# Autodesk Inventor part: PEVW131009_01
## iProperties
Created: 2009-10
Part Number: PEVW131009_01
Cost Center: 0 kg
Material: 1.0037 St 37-2
Document SubType Name: Blech
Designer: Student_TAB
Authority: 0 mm^3
Density: 7.85 g/cm^3
Description: Test Abgeleitete Komponente iPart
Mass: 200.159 g
Surface Area: 687.763 cm^2
Volume: 25.498 cm^3
SaveDate: 2007-07-03
SaveTime: 10:26
TotalMass: 0 kg
TotalVolume: 0 mm^3
Author: Student_TAB
Title: Test Abgeleitete Komponente iPart
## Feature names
1. Grobblech1
2. Grobblech2
3. Biegung1
